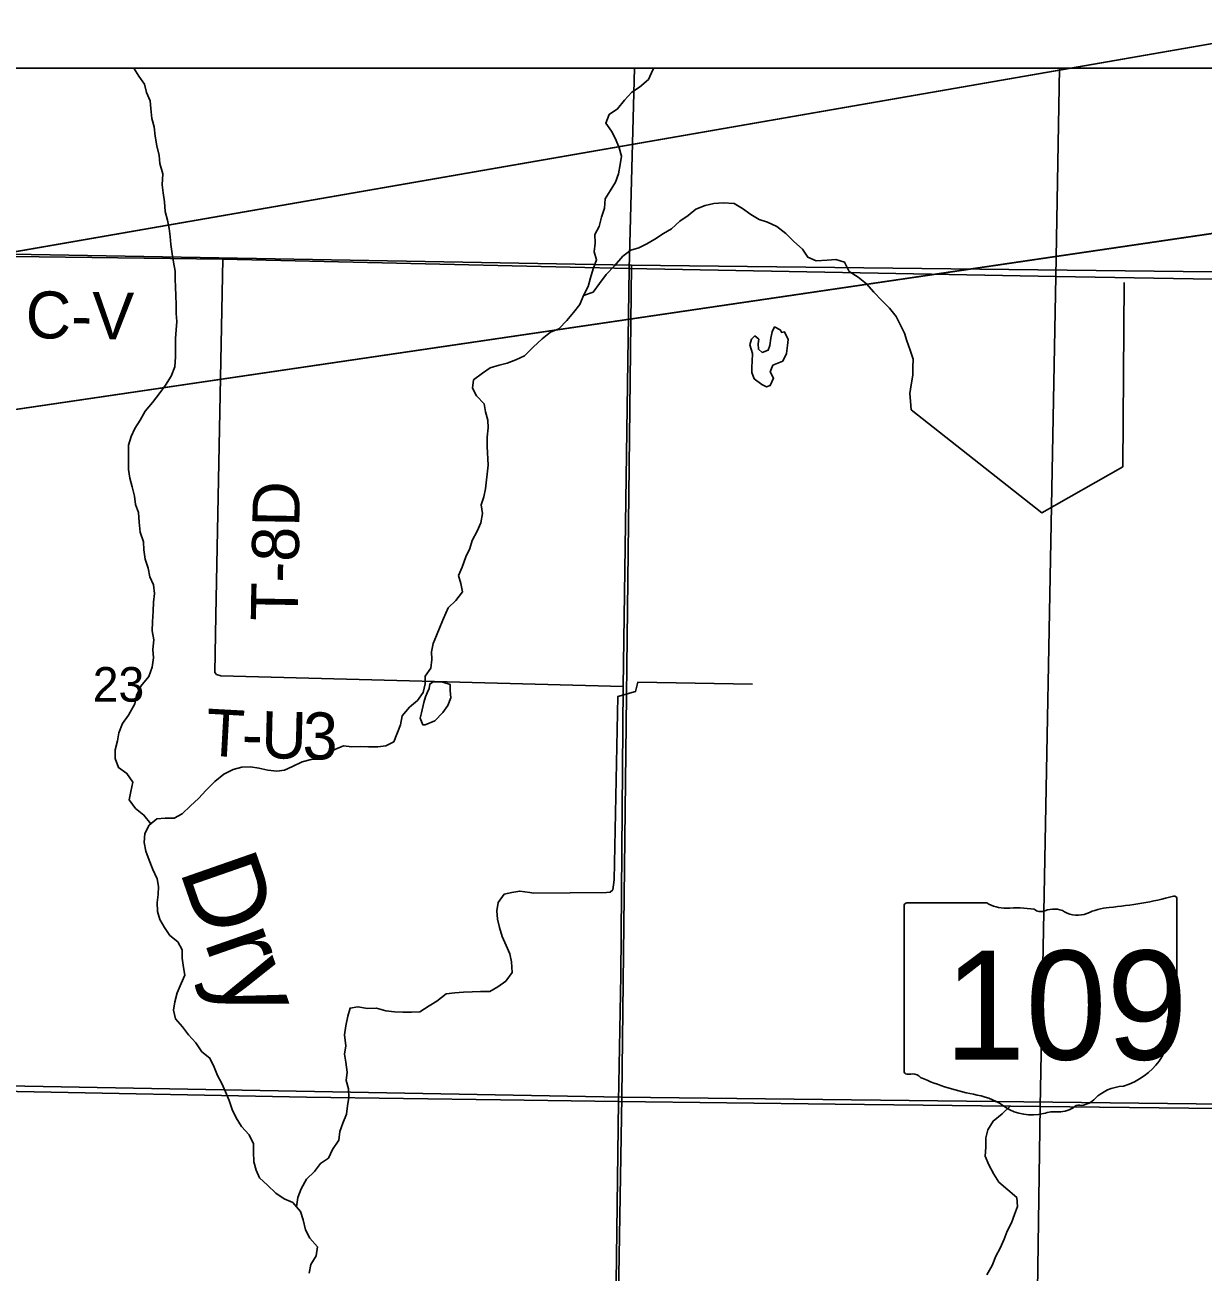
# Model space of a CAD drawing. Extents: x -6.2 to 37.4, y 0.2 to 22.2.
# Drawn here: x 6.014 to 6.726, y 20.38 to 21.133 of the extents above; entities that cross this region are included whole.
import ezdxf

# ---------------------------------------------------------------- set-up
doc = ezdxf.new("R2010")
doc.units = 0
for name, color, linetype in [('GM_X_County_Road', 7, 'Continuous'), ('GM_X_County_Road_Text', 7, 'Continuous'), ('GM_X_Minor_Lake', 7, 'Continuous'), ('GM_X_Minor_River', 7, 'Continuous'), ('GM_X_Minor_River_Text', 7, 'Continuous'), ('GM_X_Rail_Line', 7, 'Continuous'), ('GM_X_Section', 7, 'Continuous'), ('GM_X_Section_Text', 7, 'Continuous'), ('GM_X_State_Location', 7, 'Continuous'), ('GM_X_State_Route', 7, 'Continuous'), ('GM_X_State_Shield', 7, 'Continuous'), ('GM_X_Township_Road', 7, 'Continuous'), ('GM_X_Township_Road_Text', 7, 'Continuous'), ('SH_Border', 7, 'Continuous'), ('SH_Data', 7, 'Continuous')]:
    doc.layers.add(name, color=color, linetype=linetype)

msp = doc.modelspace()

# ---------------------------------------------------------------- linework, layer by layer
at = {"layer": 'GM_X_County_Road'}
for points in [[(5.38316, 20.98677), (5.61779, 20.98265), (5.63201, 20.9834), (5.73462, 20.98828), (5.8801, 20.99504), (6.13384, 20.9918), (6.3438, 20.98708), (6.37943, 20.9862), (6.63731, 20.98139)], [(6.63731, 20.98139), (6.79139, 20.97877), (6.8905, 20.9813)], [(5.87032, 20.49219), (5.89779, 20.49087), (5.94232, 20.48989), (5.99939, 20.4888), (6.18449, 20.48528), (6.3018, 20.4837), (6.37305, 20.48273), (6.504, 20.48097), (6.62788, 20.47969), (6.87943, 20.47678)]]:
    msp.add_lwpolyline(points, dxfattribs=at)
at = {"layer": 'GM_X_Minor_Lake'}
for p, q in [((6.45498, 20.91944), (6.45964, 20.91612)), ((6.25638, 20.72728), (6.25536, 20.72389))]:
    msp.add_line(p, q, dxfattribs=at)
for points in [[(6.45964, 20.91612), (6.46245, 20.91474), (6.46474, 20.91545), (6.46673, 20.91996), (6.46472, 20.9238), (6.46632, 20.92775), (6.47224, 20.93028), (6.47461, 20.93479), (6.47509, 20.93971), (6.47554, 20.94331), (6.47337, 20.9479), (6.47166, 20.94756), (6.47074, 20.94909), (6.46737, 20.95087), (6.4658, 20.94787), (6.46515, 20.94409), (6.46449, 20.93974), (6.46348, 20.93691), (6.45986, 20.93546), (6.45763, 20.93741), (6.45751, 20.94063), (6.45775, 20.94347), (6.45533, 20.94542), (6.4534, 20.94356), (6.45238, 20.93998), (6.45398, 20.93482), (6.45388, 20.93008), (6.45362, 20.92667), (6.45355, 20.92326), (6.45498, 20.91944)], [(6.25536, 20.72389), (6.2539, 20.71766), (6.25308, 20.71445), (6.2547, 20.71043), (6.25621, 20.7104), (6.26213, 20.71275), (6.26697, 20.71778), (6.2699, 20.72208), (6.2717, 20.7266), (6.27122, 20.73116), (6.2713, 20.73476), (6.26679, 20.73618), (6.26395, 20.73643), (6.26054, 20.73611), (6.259, 20.73501), (6.25857, 20.73236), (6.25738, 20.72973), (6.25638, 20.72728)]]:
    msp.add_lwpolyline(points, dxfattribs=at)
at = {"layer": 'GM_X_Minor_River'}
for points in [[(6.09049, 20.65059), (6.08624, 20.65578), (6.08121, 20.65986), (6.07735, 20.66506), (6.07839, 20.66997), (6.07946, 20.67564), (6.07598, 20.68102), (6.07094, 20.68454), (6.06878, 20.69008), (6.06889, 20.6952), (6.07033, 20.70067), (6.071, 20.70559), (6.07339, 20.71123), (6.0769, 20.71609), (6.08083, 20.72303), (6.0817, 20.72814), (6.08446, 20.73377), (6.08913, 20.73956), (6.09114, 20.74521), (6.09201, 20.75088), (6.09155, 20.75582), (6.09224, 20.76169), (6.09122, 20.76721), (6.09152, 20.77252), (6.09185, 20.77915), (6.09196, 20.78446), (6.09264, 20.78976), (6.09199, 20.79508), (6.08982, 20.79987), (6.0888, 20.80501), (6.08702, 20.81055), (6.08619, 20.81606), (6.08591, 20.821), (6.08396, 20.82692), (6.08332, 20.83281), (6.08288, 20.8387), (6.08108, 20.84348), (6.08062, 20.84861), (6.07923, 20.85414), (6.07782, 20.85948), (6.07699, 20.86462), (6.07691, 20.86993), (6.07701, 20.87467), (6.07692, 20.87942), (6.07854, 20.8847), (6.08073, 20.88959), (6.08404, 20.89445), (6.087, 20.89989), (6.09146, 20.90511), (6.09536, 20.91035), (6.09926, 20.91577), (6.10278, 20.9212), (6.10498, 20.92685), (6.10529, 20.93291), (6.10542, 20.93879), (6.10533, 20.94391), (6.10582, 20.94921), (6.10612, 20.95414), (6.10565, 20.95908), (6.10576, 20.9642), (6.1055, 20.9699), (6.10542, 20.97502), (6.10514, 20.97977), (6.10505, 20.98451), (6.10403, 20.99004), (6.10338, 20.99498), (6.10255, 21.00069), (6.10208, 21.00563), (6.10143, 21.01038), (6.1004, 21.01534), (6.09899, 21.02068), (6.09874, 21.02656), (6.0979, 21.03189), (6.09725, 21.03684), (6.09758, 21.04347), (6.09582, 21.04977), (6.09554, 21.05451), (6.09396, 21.06043), (6.09313, 21.06613), (6.09249, 21.07184), (6.09108, 21.0768), (6.09046, 21.08288), (6.08999, 21.08763), (6.08782, 21.09261), (6.0866, 21.09756), (6.08311, 21.10257), (6.08018, 21.10737), (6.08014, 21.10742)], [(6.29433, 20.86742), (6.29362, 20.87867), (6.29374, 20.88417), (6.29423, 20.88985), (6.29414, 20.89459), (6.29273, 20.89955), (6.29189, 20.90431), (6.28726, 20.90915), (6.28471, 20.91394), (6.28538, 20.91886), (6.29076, 20.92293), (6.29556, 20.92624), (6.3009, 20.92784), (6.30565, 20.92908), (6.311, 20.93106), (6.31616, 20.93342), (6.32138, 20.93863), (6.32697, 20.94363), (6.33198, 20.94771), (6.33694, 20.94969), (6.34178, 20.95472), (6.34585, 20.95957), (6.34974, 20.96442), (6.35194, 20.96988), (6.3547, 20.97533), (6.35613, 20.98061), (6.35776, 20.98608), (6.35977, 20.99154), (6.35836, 20.99631), (6.35885, 21.00161), (6.35876, 21.00673), (6.36133, 21.01162), (6.36277, 21.01728), (6.36459, 21.02274), (6.36489, 21.02824), (6.36802, 21.03311), (6.37116, 21.03836), (6.37297, 21.04344), (6.37404, 21.04911), (6.3749, 21.05422), (6.37349, 21.05918), (6.37114, 21.06453), (6.36878, 21.06932), (6.36529, 21.07414), (6.36748, 21.0794), (6.37247, 21.08272), (6.37674, 21.08795), (6.38101, 21.09279), (6.38581, 21.09592), (6.39121, 21.10055), (6.39379, 21.10638), (6.39438, 21.10742)], [(6.35194, 20.96988), (6.35766, 20.97185), (6.36155, 20.97709), (6.36564, 20.9825), (6.37067, 20.98791), (6.37572, 20.99368), (6.38052, 20.99738), (6.38529, 20.9988), (6.39007, 21.00117), (6.39505, 21.00392), (6.40023, 21.00742), (6.40502, 21.01017), (6.41004, 21.01481), (6.41503, 21.01831), (6.41984, 21.02201), (6.42538, 21.02437), (6.43071, 21.02559), (6.4362, 21.02586), (6.44301, 21.02553), (6.44806, 21.02258), (6.45309, 21.01888), (6.45794, 21.01575), (6.46302, 21.01413), (6.46864, 21.01155), (6.47405, 21.00746), (6.47906, 21.00261), (6.48426, 20.99795), (6.48738, 20.99315), (6.49244, 20.99077), (6.49907, 20.99121), (6.50438, 20.99167), (6.50965, 20.99005), (6.51237, 20.98449), (6.51778, 20.98097), (6.52281, 20.97688), (6.52724, 20.97186), (6.53188, 20.96703), (6.5367, 20.96219), (6.54075, 20.95717), (6.5433, 20.95238), (6.54585, 20.94721), (6.54726, 20.94244), (6.54922, 20.9369), (6.551, 20.93136), (6.5509, 20.92643), (6.5508, 20.92169), (6.54992, 20.91582), (6.54906, 20.91072), (6.54952, 20.90597), (6.54998, 20.90084)], [(6.54998, 20.90084), (6.62893, 20.83855), (6.67778, 20.8664), (6.6786, 20.97774)], [(6.27846, 20.80575), (6.28087, 20.81196), (6.28324, 20.81685), (6.28467, 20.82175), (6.28762, 20.82738), (6.28981, 20.83246), (6.29088, 20.83813), (6.29004, 20.84327), (6.29166, 20.84817), (6.29271, 20.85308), (6.29433, 20.86742)], [(6.19111, 20.39476), (6.18649, 20.39997), (6.18395, 20.40515), (6.18256, 20.41105), (6.18077, 20.41621), (6.17615, 20.42161), (6.17109, 20.4238), (6.16605, 20.42732), (6.16085, 20.43216), (6.15602, 20.43643), (6.15404, 20.44122), (6.15263, 20.44617), (6.15238, 20.45225), (6.15248, 20.45699), (6.14994, 20.46254), (6.14513, 20.46757), (6.14202, 20.47275), (6.13947, 20.47774), (6.1377, 20.48327), (6.13554, 20.48844), (6.13337, 20.4936), (6.13063, 20.4984), (6.12866, 20.50337), (6.12612, 20.50892), (6.12128, 20.51262), (6.11761, 20.51801), (6.11317, 20.52303), (6.10949, 20.52784), (6.10523, 20.53267), (6.1042, 20.53781), (6.10488, 20.54292), (6.10632, 20.54839), (6.10871, 20.55403), (6.11089, 20.55892), (6.11024, 20.56368), (6.10941, 20.5692), (6.10932, 20.57432), (6.10677, 20.57911), (6.10193, 20.583), (6.09863, 20.58781), (6.09589, 20.59261), (6.09448, 20.59757), (6.09421, 20.60288), (6.09488, 20.6078), (6.09498, 20.61254), (6.09433, 20.6173), (6.0916, 20.62285), (6.08945, 20.62859), (6.08748, 20.63394), (6.08646, 20.63927), (6.08676, 20.64457), (6.08932, 20.64964), (6.09414, 20.65353), (6.09907, 20.654), (6.10456, 20.65389), (6.10934, 20.65645), (6.11437, 20.66147), (6.11919, 20.66574), (6.12384, 20.67076), (6.12906, 20.67616), (6.13445, 20.6806), (6.14019, 20.68333), (6.14533, 20.68475), (6.15063, 20.68502), (6.15573, 20.68416), (6.16119, 20.68291), (6.16648, 20.68243), (6.17122, 20.6829), (6.176, 20.68508), (6.18193, 20.688), (6.18726, 20.68941), (6.19218, 20.6895), (6.19712, 20.69054), (6.20158, 20.69538), (6.20693, 20.69774), (6.21183, 20.69707), (6.21695, 20.69716), (6.22187, 20.69706), (6.22754, 20.69713), (6.23247, 20.6976), (6.23726, 20.70016), (6.24126, 20.71032), (6.24232, 20.7158), (6.24678, 20.72103), (6.2516, 20.7251), (6.25492, 20.72997), (6.25616, 20.73506), (6.25626, 20.73981), (6.25958, 20.74467), (6.26026, 20.74978), (6.25998, 20.75453), (6.26103, 20.75944), (6.26302, 20.76433), (6.26522, 20.76979), (6.26721, 20.77468), (6.27, 20.78107), (6.27482, 20.78553), (6.27872, 20.79076), (6.27769, 20.79571), (6.27628, 20.80067), (6.27846, 20.80575)], [(6.32184, 20.60855), (6.36576, 20.609), (6.36803, 20.60914), (6.36958, 20.61063), (6.37002, 20.61365), (6.37046, 20.61668), (6.3726, 20.72741), (6.38326, 20.73042), (6.3847, 20.73609), (6.45395, 20.73489)], [(6.17847, 20.4189), (6.17924, 20.42459), (6.18125, 20.42986), (6.1844, 20.43567), (6.18942, 20.44031), (6.19292, 20.44517), (6.19772, 20.4483), (6.20029, 20.45356), (6.20401, 20.45918), (6.20469, 20.46447), (6.2065, 20.46956), (6.20869, 20.47502), (6.20936, 20.47993), (6.21004, 20.48504), (6.20977, 20.49036), (6.20855, 20.49531), (6.20904, 20.50042), (6.20821, 20.50632), (6.20737, 20.51127), (6.20823, 20.51637), (6.20743, 20.52303), (6.2083, 20.52832), (6.20937, 20.53418), (6.21079, 20.53908), (6.21554, 20.53994), (6.22139, 20.53887), (6.22688, 20.53914), (6.23234, 20.53751), (6.23762, 20.53684), (6.24273, 20.53673), (6.24803, 20.53663), (6.25296, 20.53691), (6.25852, 20.5404), (6.26331, 20.54334), (6.26889, 20.54778), (6.27421, 20.54843), (6.27932, 20.54871), (6.28463, 20.54898), (6.28955, 20.54907), (6.29523, 20.54915), (6.30021, 20.55189), (6.30501, 20.5554), (6.30872, 20.56063), (6.30829, 20.56709), (6.30744, 20.57185), (6.30509, 20.57702), (6.30274, 20.58238), (6.30115, 20.58791), (6.29993, 20.59287), (6.29947, 20.59781), (6.30033, 20.60291), (6.30385, 20.60796), (6.3086, 20.60901), (6.31335, 20.60986), (6.31939, 20.60898), (6.32184, 20.60855)], [(6.59561, 20.3779), (6.59876, 20.38353), (6.60115, 20.38917), (6.60371, 20.39405), (6.60609, 20.39932), (6.6079, 20.40421), (6.61047, 20.40928), (6.61228, 20.41436), (6.61408, 20.41926), (6.61381, 20.42458), (6.60823, 20.42924), (6.60284, 20.4339), (6.59992, 20.4387), (6.59681, 20.44427), (6.59466, 20.44962), (6.59496, 20.45511), (6.59508, 20.46061), (6.59612, 20.46552), (6.59945, 20.47077), (6.60485, 20.47521), (6.60967, 20.47986)], [(6.18605, 20.37893), (6.1871, 20.38403), (6.19024, 20.38928), (6.19111, 20.39476)]]:
    msp.add_lwpolyline(points, dxfattribs=at)
at = {"layer": 'GM_X_Rail_Line'}
msp.add_lwpolyline([(6.86104, 19.5138), (6.86366, 19.68706), (6.86448, 19.72092), (6.86811, 19.85399), (6.87013, 19.97553), (6.87027, 19.97886), (6.87188, 20.07204), (6.87223, 20.09839), (6.87931, 20.47706), (6.87948, 20.48391), (6.88449, 20.73399), (6.89038, 20.98158), (6.89238, 21.10742), (5.08086, 21.10742), (5.08086, 18.73488)], dxfattribs=at)
at = {"layer": 'GM_X_Section'}
for points in [[(6.38094, 20.98831), (6.37505, 20.48536), (5.87199, 20.49448), (5.88186, 20.99717)], [(6.88974, 20.98243), (6.87834, 20.48385), (6.87843, 20.47933), (6.37505, 20.48536), (6.38094, 20.98831)], [(5.87199, 20.49448), (6.37505, 20.48536), (6.36649, 19.98171), (5.86238, 19.98478)], [(6.37505, 20.48536), (6.87843, 20.47933), (6.86829, 19.98023), (6.36649, 19.98171)]]:
    msp.add_lwpolyline(points, close=True, dxfattribs=at)
at = {"layer": 'GM_X_State_Route'}
msp.add_lwpolyline([(6.62348, 20.22981), (6.6259, 20.34062), (6.62788, 20.47969), (6.63731, 20.98139), (6.63952, 21.10742)], dxfattribs=at)
at = {"layer": 'GM_X_State_Shield'}
for p, q in [((6.71049, 20.5528), (6.71049, 20.60514)), ((6.5457, 20.60094), (6.5457, 20.50088)), ((6.59558, 20.60266), (6.54732, 20.60266)), ((6.71047, 20.55281), (6.71049, 20.5528))]:
    msp.add_line(p, q, dxfattribs=at)
for centre, major_axis, start_param, end_param in [((6.65179, 20.73908), (0.17476, 0), 4.814394, 5.042369), ((6.70866, 20.60536), (0.00183, 0), 6.141152, 7.989035), ((6.54758, 20.60115), (0.00191, 0), 1.712693, 3.28349), ((6.60707, 20.61428), (0.01852, 0), 4.042523, 4.731795), ((6.61321, 20.54649), (0.06648, 0), 1.404758, 1.657858), ((6.6283, 20.60167), (0.00534, 0), 3.836095, 5.185415), ((6.63615, 20.59011), (0.01111, 0), 0.950623, 2.079405), ((6.65048, 20.60597), (0.01336, 0), 4.081561, 5.145723), ((6.67408, 20.5721), (0.03516, 0), 1.699011, 2.107814), ((6.70853, 20.5526), (0.00196, 0), 5.05454, 6.418171), ((6.71006, 20.54896), (0.00284, 0), 1.883978, 3.671073), ((6.692, 20.54234), (0.01704, 0), 5.934695, 6.695948), ((6.71706, 20.53089), (0.0124, 0), 2.387724, 3.262537), ((6.66158, 20.52423), (0.04371, 0), 5.101752, 6.440018), ((6.5476, 20.50066), (0.00193, 0), 3.00124, 4.508301), ((6.54789, 20.5109), (0.0147, 0), 4.665946, 4.897461), ((6.5509, 20.49511), (0.0053, 0), 0.519207, 1.627899), ((6.61781, 20.58501), (0.1262, 0), 4.195997, 4.488961), ((6.68001, 20.47279), (0.02394, 0), 1.647645, 2.488434), ((6.58019, 20.45593), (0.03949, 0), 0.823519, 1.323587), ((6.64968, 20.49118), (0.01412, 0), 4.937069, 5.64225), ((6.62289, 20.49461), (0.02506, 0), 4.026481, 4.996735), ((6.63737, 20.46002), (0.02059, 0), 1.495662, 1.94098), ((6.6392, 20.48712), (0.01335, 0), 4.691044, 5.507374), ((6.65128, 20.47743), (0.00376, 0), 1.147584, 2.315152)]:
    msp.add_ellipse(centre, major_axis=major_axis, ratio=0.8, start_param=start_param, end_param=end_param, dxfattribs=at)
at = {"layer": 'GM_X_Township_Road'}
for p, q in [((6.37943, 20.9862), (6.38266, 21.10742)), ((6.12974, 20.77635), (6.13384, 20.9918)), ((6.12908, 20.74207), (6.12974, 20.77635))]:
    msp.add_line(p, q, dxfattribs=at)
for points in [[(6.37305, 20.48273), (6.37448, 20.55883), (6.37576, 20.73362), (6.37943, 20.9862)], [(6.12908, 20.74207), (6.1302, 20.74073), (6.13266, 20.73994), (6.37576, 20.73362)], [(6.36969, 20.22883), (6.36974, 20.23225), (6.37305, 20.48273)]]:
    msp.add_lwpolyline(points, dxfattribs=at)
at = {"layer": 'SH_Border'}
for p, q in [((2.46928, 20.38039), (9.08657, 21.53204)), ((9.08657, 21.35383), (2.46928, 20.38039))]:
    msp.add_line(p, q, dxfattribs=at)
at = {"layer": 'SH_Data'}
msp.add_line((1.68086, 21.10742), (8.48086, 21.10742), dxfattribs=at)
msp.add_lwpolyline([(9.08657, 21.35383), (2.46928, 20.38039), (9.08657, 21.53204)], close=True, dxfattribs=at)

# ---------------------------------------------------------------- texts
at = {"layer": 'GM_X_County_Road_Text'}
msp.add_text('C-V', height=0.028409, rotation=359.2032, dxfattribs=at).set_placement((6.01463, 20.94412))
at = {"layer": 'GM_X_Minor_River_Text'}
msp.add_text('Dry', height=0.047378, rotation=289.22197, dxfattribs=at).set_placement((6.10746, 20.62265))
at = {"layer": 'GM_X_Section_Text'}
msp.add_text('23', height=0.020928, rotation=0.00001, dxfattribs=at).set_placement((6.05531, 20.72434))
at = {"layer": 'GM_X_State_Location'}
for s in ['s', 'r']:
    msp.add_text(s, height=0.0000947, dxfattribs=at).set_placement((6.62624, 20.54426))
msp.add_text('109', height=0.0000947, rotation=0.00001, dxfattribs=at).set_placement((6.59281, 20.53737))
at = {"layer": 'GM_X_State_Shield'}
msp.add_text('109', height=0.065918, dxfattribs=at).set_placement((6.56993, 20.50794))
at = {"layer": 'GM_X_Township_Road_Text'}
for s, height, rotation, p in [('T-8D', 0.028409, 89.04662, (6.1792, 20.77293)), ('T', 0.02841, 356.84418, (6.12303, 20.69183)), ('U', 0.02841, 358.6361, (6.15688, 20.6903)), ('3', 0.02841, 358.69854, (6.18191, 20.6897)), ('-', 0.02841, 358.44178, (6.14511, 20.69062))]:
    msp.add_text(s, height=height, rotation=rotation, dxfattribs=at).set_placement(p)

doc.saveas('drawing.dxf')
